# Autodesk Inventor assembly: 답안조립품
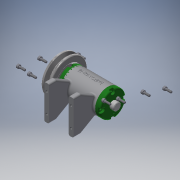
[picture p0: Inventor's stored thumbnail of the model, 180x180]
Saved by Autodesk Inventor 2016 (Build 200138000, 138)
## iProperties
Created: 2018-05
Part Number: 답안조립품
Material: 일반
Document SubType Name: Assembly
Designer: 201-08
Author: 201-08
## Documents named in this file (9)
- C:\Users\201-08\Desktop\480507V1004\답안조립품.iam
- C:\Users\201-08\Desktop\480507V1004\본체.ipt
- C:\Users\201-08\Desktop\480507V1004\V벨트풀리.ipt
- C:\Users\201-08\Desktop\480507V1004\너트 M8.ipt
- C:\Users\201-08\Desktop\480507V1004\베어링 6002.ipt
- C:\Users\201-08\Desktop\480507V1004\축.ipt
- C:\Users\201-08\Desktop\480507V1004\앞커버.ipt
- C:\Users\201-08\Desktop\480507V1004\뒤커버.ipt
- C:\Users\201-08\Desktop\480507V1004\볼트 M4x12.ipt
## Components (1 placed, 1 different names)
1. V벨트풀리:1
